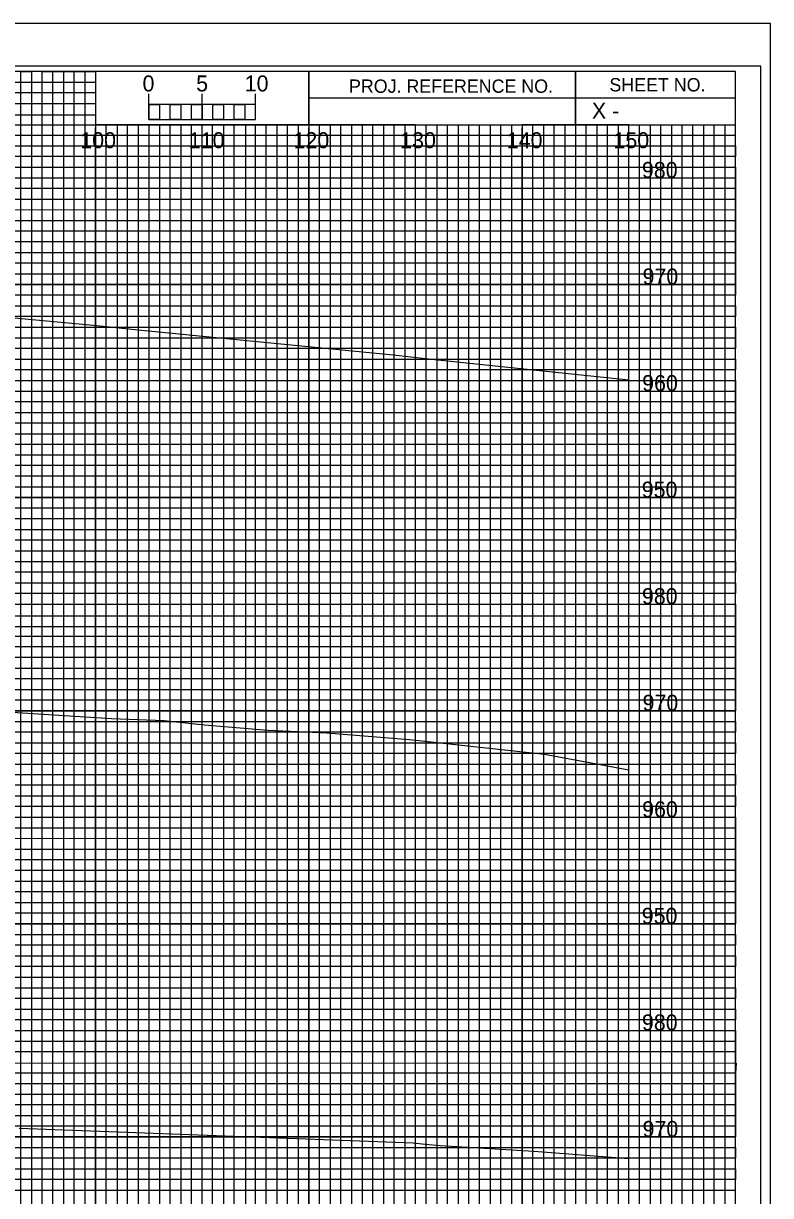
# Model space of a CAD drawing. Extents: x -13 to 760, y -5 to 1491.
# Drawn here: x 253.2 to 323.3, y 1380.5 to 1490.5 of the extents above; entities that cross this region are included whole.
import ezdxf

# ---------------------------------------------------------------- set-up
doc = ezdxf.new("R2010")
doc.units = 0
for name, color, linetype in [('Exist XS Ground Line', 7, 'Continuous'), ('Prop XS Elevation Labels', 7, 'Continuous'), ('Prop XS Offset Labels', 7, 'Continuous'), ('Sheet Cross Section CELL', 7, 'Continuous'), ('Sheet Cross Section Grid Major CELL', 7, 'Continuous'), ('Sheet Cross Section Grid Middle CELL', 7, 'Continuous'), ('Sheet Cross Section Grid Minor 1 CELL', 7, 'Continuous'), ('Sheet Cross Section Grid Minor 2 CELL', 7, 'Continuous'), ('Sheet Cross Section Scale CELL', 7, 'Continuous'), ('Sheet Cutting Line CELL', 7, 'Continuous'), ('Sheet DOT Grid CELL', 7, 'Continuous'), ('Sheet Plot Border Inside CELL', 7, 'Continuous'), ('Sheet Plot Border Outside CELL', 7, 'Continuous')]:
    doc.layers.add(name, color=color, linetype=linetype)

msp = doc.modelspace()

# ---------------------------------------------------------------- linework, layer by layer
at = {"layer": 'Exist XS Ground Line'}
for points in [[(247.29, 1463.35), (259.82, 1462.2), (264.3, 1461.73), (287.9, 1459.41), (291.24, 1459.06), (310, 1457.06)], [(247.29, 1463.35), (259.82, 1462.2), (264.3, 1461.73), (287.9, 1459.41), (291.24, 1459.06), (310, 1457.06)], [(247.25, 1426.19), (261.5, 1425.29), (266.43, 1425.09), (270.21, 1424.7), (272.45, 1424.5), (276.2, 1424.2), (281.7, 1423.94), (289.45, 1423.32), (302.11, 1421.93), (310, 1420.46)], [(247.25, 1426.19), (261.5, 1425.29), (266.43, 1425.09), (270.21, 1424.7), (272.45, 1424.5), (276.2, 1424.2), (281.7, 1423.94), (289.45, 1423.32), (302.11, 1421.93), (310, 1420.46)], [(252.84, 1386.84), (289.8, 1385.46), (290.91, 1385.35), (292.31, 1385.23), (301.1, 1384.7), (310, 1384)], [(252.84, 1386.84), (289.8, 1385.46), (290.91, 1385.35), (292.31, 1385.23), (301.1, 1384.7), (310, 1384)]]:
    msp.add_lwpolyline(points, dxfattribs=at)
at = {"layer": 'Sheet Cross Section CELL'}
for p, q in [((305, 1486.02), (305, 1481.02)), ((305, 1481.02), (305, 1486.02)), ((280, 1483.52), (280, 1481.02)), ((320, 1483.51), (280, 1483.51)), ((280, 1481.02), (320, 1481.02))]:
    msp.add_line(p, q, dxfattribs=at)
for points in [[(320, 1486.02), (0, 1486.02), (0, 1276.02), (320, 1276.02)], [(280, 1486.02), (260, 1486.02), (260, 1481.05), (280, 1481.05)], [(320, 1486.02), (280, 1486.02), (280, 1481.02), (320, 1481.02)]]:
    msp.add_lwpolyline(points, close=True, dxfattribs=at)
at = {"layer": 'Sheet Cross Section Grid Major CELL'}
for p, q in [((260, 1486.02), (260, 1276.02)), ((270, 1276.02), (270, 1481.02)), ((290, 1481.02), (280, 1481.02)), ((280, 1481.02), (280, 1276.02)), ((290, 1276.02), (290, 1481.02)), ((310, 1481.02), (300, 1481.02)), ((300, 1481.02), (300, 1276.02)), ((310, 1276.02), (310, 1481.02))]:
    msp.add_line(p, q, dxfattribs=at)
for points in [[(0, 1476.02), (320, 1476.02), (320, 1466.02), (0, 1466.02)], [(0, 1456.02), (320, 1456.02), (320, 1446.02), (0, 1446.02)], [(0, 1436.02), (320, 1436.02), (320, 1426.02), (0, 1426.02)], [(0, 1416.02), (320, 1416.02), (320, 1406.02), (0, 1406.02)], [(0, 1396.02), (320, 1396.02), (320, 1386.02), (0, 1386.02)]]:
    msp.add_lwpolyline(points, dxfattribs=at)
at = {"layer": 'Sheet Cross Section Grid Middle CELL'}
for points in [[(255, 1276.02), (255, 1486.02), (259.93, 1486.02), (260, 1486.02), (260, 1481.02), (264.99, 1481.02), (264.99, 1276.02)], [(0, 1481.02), (275, 1481.02)], [(275, 1276.02), (275, 1481.02), (285, 1481.02), (285, 1276.02)], [(295, 1276.02), (295, 1481.02), (305, 1481.02), (305, 1276.02)], [(315, 1276.02), (315, 1481.02)], [(0, 1461.02), (320, 1461.02), (320, 1471.02), (0, 1471.02)], [(0, 1441.02), (320, 1441.02), (320, 1451.02), (0, 1451.02)], [(0, 1421.02), (320, 1421.02), (320, 1431.02), (0, 1431.02)], [(0, 1401.02), (320, 1401.02), (320, 1411.02), (0, 1411.02)], [(0, 1381.02), (320, 1381.02), (320, 1391.02), (0, 1391.02)]]:
    msp.add_lwpolyline(points, dxfattribs=at)
at = {"layer": 'Sheet Cross Section Grid Minor 1 CELL'}
for p, q in [((0, 1485.02), (260, 1485.02)), ((260, 1485.02), (260, 1484)), ((260, 1484), (0, 1484)), ((0, 1483.02), (260, 1483.02)), ((260, 1483.02), (260, 1481.91)), ((260, 1481.91), (0, 1481.91)), ((0, 1480.02), (320, 1480.02))]:
    msp.add_line(p, q, dxfattribs=at)
for points in [[(0, 1479.02), (270, 1479.02), (320, 1479.02), (320, 1478.02), (0, 1478.02)], [(0, 1477.02), (320, 1477.02), (320, 1475.02), (0, 1475.02)], [(0, 1474.02), (320, 1474.02), (320, 1473.02), (0, 1473)], [(0, 1472.02), (320, 1472.02), (320, 1470.02), (0, 1470.02)], [(0, 1469.02), (320, 1469.02), (320, 1468.02), (0, 1468.02)], [(0, 1467.02), (320, 1467.02), (320, 1465.02), (0, 1465.02)], [(0, 1464.02), (320, 1464.02), (320, 1463.02), (0, 1463.02)], [(0, 1462.02), (320, 1462.02), (320, 1460.02), (0, 1460.02)], [(0, 1459.02), (320, 1459.02), (320, 1458.02), (0, 1458.02)], [(0, 1457.02), (320, 1457.02), (320, 1455.02), (0, 1455.02)], [(0, 1454.02), (320, 1454.02), (320, 1453.02), (0, 1453.02)], [(0, 1452.02), (320, 1452.02), (320, 1449.97), (320, 1449.02), (320, 1448.02), (0, 1448.02)], [(0, 1450.02), (320, 1450.02), (320, 1449.02), (0, 1449.02)], [(0, 1447.02), (320, 1447.02), (320, 1445.02), (0, 1445.05)], [(0, 1445.05), (320, 1445.02), (320, 1444.02), (0, 1444.02)], [(0, 1443.02), (320, 1443.02), (320, 1442.02), (0, 1442.02)], [(0, 1440.02), (320, 1440.02), (320, 1439.02), (0, 1439.02)], [(0, 1438.02), (320, 1438.02), (320, 1437.02), (0, 1437.02)], [(-0.07, 1434.91), (320, 1434.91), (320, 1433.9), (-0.07, 1433.9)], [(0, 1433.02), (320, 1433.02), (320, 1432.02), (0, 1432.02)], [(0, 1430.02), (320, 1430.02), (320, 1429.02), (0, 1429.02)], [(0, 1428.02), (320, 1428.02), (320, 1427.02), (0, 1427.02)], [(0, 1425.02), (320, 1425.02), (320, 1424.02), (0, 1424.02)], [(0, 1423.02), (320, 1423.02), (320, 1422.02), (0, 1422.02)], [(0, 1420.02), (320, 1420.02), (320, 1419.02), (0, 1419.02)], [(0, 1418.02), (320, 1418.02), (320, 1417.02), (0, 1417.02)], [(0, 1415.02), (320, 1415.02), (319.99, 1414), (0, 1414.02)], [(0, 1413.02), (320, 1413.02), (320, 1412.02), (0, 1412.02)], [(0, 1410.02), (320, 1410.02), (320, 1409.02), (0, 1409.02)], [(0, 1408.02), (320, 1408.02), (320, 1407.02), (0, 1407.02)], [(0, 1405.02), (320, 1405.02), (320, 1404.02), (0, 1404.02)], [(0, 1403.02), (320, 1403.02), (320, 1402.02), (0, 1402.02)], [(0, 1400.02), (320, 1400.02), (320, 1399.02), (0, 1399.02)], [(0, 1398.02), (320, 1398.02), (320, 1397.02), (0, 1397.02)], [(0, 1395.02), (320, 1395.02), (320, 1394.02), (0, 1394.02)], [(0, 1393.01), (320.07, 1392.93), (320, 1392.02), (0, 1392.02)], [(0, 1390.02), (320, 1390.02), (320, 1389.02), (0, 1389.02)], [(0, 1388.02), (320, 1388.02), (320, 1387.02), (0, 1387.02)], [(0, 1385.02), (320, 1385.02), (320, 1384.02), (0, 1384.02)], [(0, 1383.02), (320, 1383.02), (320, 1382.02), (0, 1382.02)]]:
    msp.add_lwpolyline(points, dxfattribs=at)
at = {"layer": 'Sheet Cross Section Grid Minor 2 CELL'}
for p, q in [((267, 1481.02), (266.01, 1481.02)), ((266.01, 1481.02), (266.01, 1276.02)), ((267, 1276.02), (267, 1481.02)), ((269, 1481.02), (268, 1481.02)), ((268, 1481.02), (268, 1276.02)), ((269, 1276.02), (269, 1481.02))]:
    msp.add_line(p, q, dxfattribs=at)
for points in [[(252, 1276.02), (253, 1276.02), (253, 1486.02), (254, 1486.02), (254, 1276.02)], [(255, 1276.02), (256, 1276.02), (256, 1486.02), (257, 1486.02), (257, 1276.02)], [(257, 1276.02), (258, 1276.02), (258, 1486.02), (259, 1486.02), (259, 1276.02)], [(260, 1276.02), (261, 1276.02), (261, 1481.02), (262.02, 1481.02), (262.02, 1276.02)], [(262, 1276.02), (263, 1276.02), (263, 1481.02), (263.99, 1481.02), (263.99, 1276.02)], [(270, 1276.02), (270.98, 1276.02), (270.98, 1481.02), (272, 1481.02), (272, 1276.02)], [(272, 1276.02), (273, 1276.02), (273, 1481.02), (274.05, 1481.02), (274.05, 1276.02)], [(275, 1276.02), (276, 1276.02), (276, 1481.02), (277, 1481.02), (277, 1276.02)], [(277, 1276.02), (278, 1276.02), (278, 1481.02), (279, 1481.02), (279, 1276.02)], [(280, 1276.02), (281, 1276.02), (281, 1481.02), (282, 1481.02), (282, 1276.02)], [(282, 1276.02), (283, 1276.02), (283, 1481.02), (284, 1481.02), (284, 1276.02)], [(285, 1276.02), (286, 1276.02), (286, 1481.02), (287, 1481.02), (287, 1276.02)], [(287, 1276.02), (288, 1276.02), (288, 1481.02), (289, 1481.02), (289, 1276.02)], [(290, 1276.02), (291, 1276.02), (291, 1481.02), (292, 1481.02), (292, 1276.02)], [(292, 1276.02), (293, 1276.02), (293, 1481.02), (294, 1481.02), (294, 1276.02)], [(295, 1276.02), (296, 1276.02), (296, 1481.02), (297, 1481.02), (297, 1276.02)], [(297, 1276.02), (298, 1276.02), (298, 1481.02), (299, 1481.02), (299, 1276.02)], [(300, 1276.02), (301, 1276.02), (301, 1481.02), (302, 1481.02), (302, 1276.02)], [(302, 1276.02), (303, 1276.02), (303, 1481.02), (304, 1481.02), (304, 1276.02)], [(305, 1276.02), (306, 1276.02), (306, 1481.02), (307, 1481.02), (307, 1276.02)], [(307, 1276.02), (308, 1276.02), (308, 1481.02), (309, 1481.02), (309, 1276.02)], [(310, 1276.02), (311, 1276.02), (311, 1481.02), (312, 1481.02), (312, 1276.02)], [(312, 1276.02), (313, 1276.02), (313, 1481.02), (314, 1481.02), (314, 1276.02)], [(315, 1276.02), (316, 1276.02), (316, 1481.02), (317, 1481.02), (317, 1276.02)], [(317, 1276.02), (318, 1276.02), (318, 1481.02), (319, 1481.02), (319, 1276.02)]]:
    msp.add_lwpolyline(points, dxfattribs=at)
at = {"layer": 'Sheet Cross Section Scale CELL'}
for p, q in [((265, 1481.51), (265, 1483.92)), ((265, 1482.92), (265, 1483.92)), ((270, 1481.51), (270, 1483.92)), ((275, 1481.51), (275, 1483.92)), ((275, 1482.92), (275, 1483.92))]:
    msp.add_line(p, q, dxfattribs=at)
for points in [[(275, 1482.92), (265, 1482.92), (265, 1481.51), (275, 1481.51)], [(265, 1482.92), (266, 1482.92), (266, 1481.51), (265, 1481.51)], [(267, 1482.92), (268, 1482.92), (268, 1481.51), (267, 1481.51)], [(269, 1482.92), (270, 1482.92), (270, 1481.51), (269, 1481.51)], [(271, 1482.92), (272, 1482.92), (272, 1481.51), (271, 1481.51)], [(273, 1482.92), (274, 1482.92), (274, 1481.51), (273, 1481.51)]]:
    msp.add_lwpolyline(points, close=True, dxfattribs=at)
at = {"layer": 'Sheet Cutting Line CELL'}
msp.add_line((323.3, 1490.52), (-13.4, 1490.52), dxfattribs=at)
at = {"layer": 'Sheet DOT Grid CELL'}
for p, q in [((260, 1276.02), (260, 1480.71)), ((270, 1276.02), (270, 1480.71)), ((280, 1276.02), (280, 1480.71)), ((290, 1276.02), (290, 1480.71)), ((300, 1276.02), (300, 1480.71)), ((310, 1276.02), (310, 1480.71)), ((0, 1476.02), (320, 1476.02)), ((0, 1466.02), (320, 1466.02)), ((0, 1456.02), (320, 1456.02)), ((0, 1446.02), (320, 1446.02)), ((0, 1436.02), (320, 1436.02)), ((0, 1426.02), (320, 1426.02)), ((0, 1416.02), (320, 1416.02)), ((0, 1406.02), (320, 1406.02)), ((0, 1396.02), (320, 1396.02)), ((0, 1386.02), (320, 1386.02))]:
    msp.add_line(p, q, dxfattribs=at)
at = {"layer": 'Sheet Plot Border Inside CELL'}
msp.add_lwpolyline([(-10.8, 1275.52), (322.4, 1275.52), (322.4, 1486.52), (-10.8, 1486.52)], close=True, dxfattribs=at)
at = {"layer": 'Sheet Plot Border Outside CELL'}
msp.add_lwpolyline([(-13.4, 1271.52), (323.3, 1271.52), (323.3, 1490.52), (-13.4, 1490.52)], close=True, dxfattribs=at)

# ---------------------------------------------------------------- texts
at = {"layer": 'Prop XS Elevation Labels'}
for s, p in [('980', (311.24, 1476.02)), ('970', (311.3, 1466.02)), ('960', (311.26, 1456.02)), ('950', (311.22, 1446.02)), ('980', (311.24, 1436.02)), ('970', (311.3, 1426.02)), ('960', (311.26, 1416.02)), ('950', (311.22, 1406.02)), ('980', (311.24, 1396.02)), ('970', (311.3, 1386.02))]:
    msp.add_text(s, height=1.5, dxfattribs=at).set_placement(p)
at = {"layer": 'Prop XS Offset Labels'}
for s, p in [('100', (258.57, 1478.81)), ('110', (268.75, 1478.81)), ('120', (278.57, 1478.81)), ('130', (288.57, 1478.81)), ('140', (298.57, 1478.81)), ('150', (308.57, 1478.81))]:
    msp.add_text(s, height=1.5, dxfattribs=at).set_placement(p)
at = {"layer": 'Sheet Cross Section CELL'}
for s, height, p in [('PROJ. REFERENCE NO.', 1.25, (283.77, 1484.01)), ('SHEET NO.', 1.25, (308.19, 1484.14)), ('X - ', 1.5, (306.55, 1481.58))]:
    msp.add_text(s, height=height, dxfattribs=at).set_placement(p)
at = {"layer": 'Sheet Cross Section Scale CELL'}
for s, p in [('0', (264.41, 1484.14)), ('5', (269.44, 1484.14)), ('10', (273.99, 1484.14))]:
    msp.add_text(s, height=1.5, dxfattribs=at).set_placement(p)

doc.saveas('drawing.dxf')
